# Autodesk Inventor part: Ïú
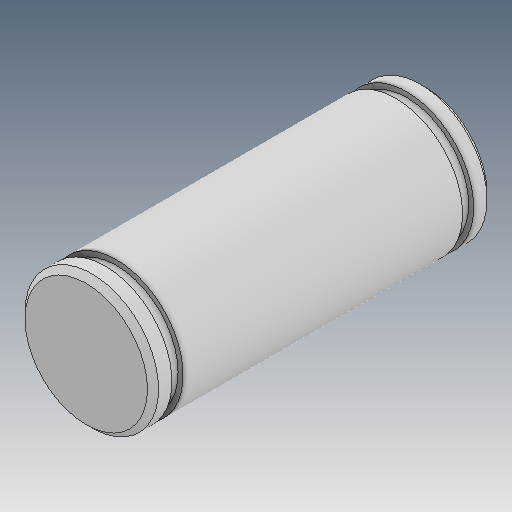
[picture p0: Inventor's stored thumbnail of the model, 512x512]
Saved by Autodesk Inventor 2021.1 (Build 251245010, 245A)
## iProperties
Created: 2019-04
Part Number: Ïú
Material: Ogólny
Document SubType Name: Modeling
Designer: user
Density: 1 g/cm^3
Appearance: Domyślna
Author: user
Revision Number: ÈÎºÎ
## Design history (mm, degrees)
feature "ÊäÈë1"
node "Bryła1"
